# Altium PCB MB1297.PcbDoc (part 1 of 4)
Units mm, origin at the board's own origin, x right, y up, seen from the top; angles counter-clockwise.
Board outline 90.1 x 62.11 mm, 4 copper layers (Top Layer, GND, POWER+GND, Bottom Layer), stack 0.778 mm thick; 235 components, 174 nets, 1727 pads, 1 vias.
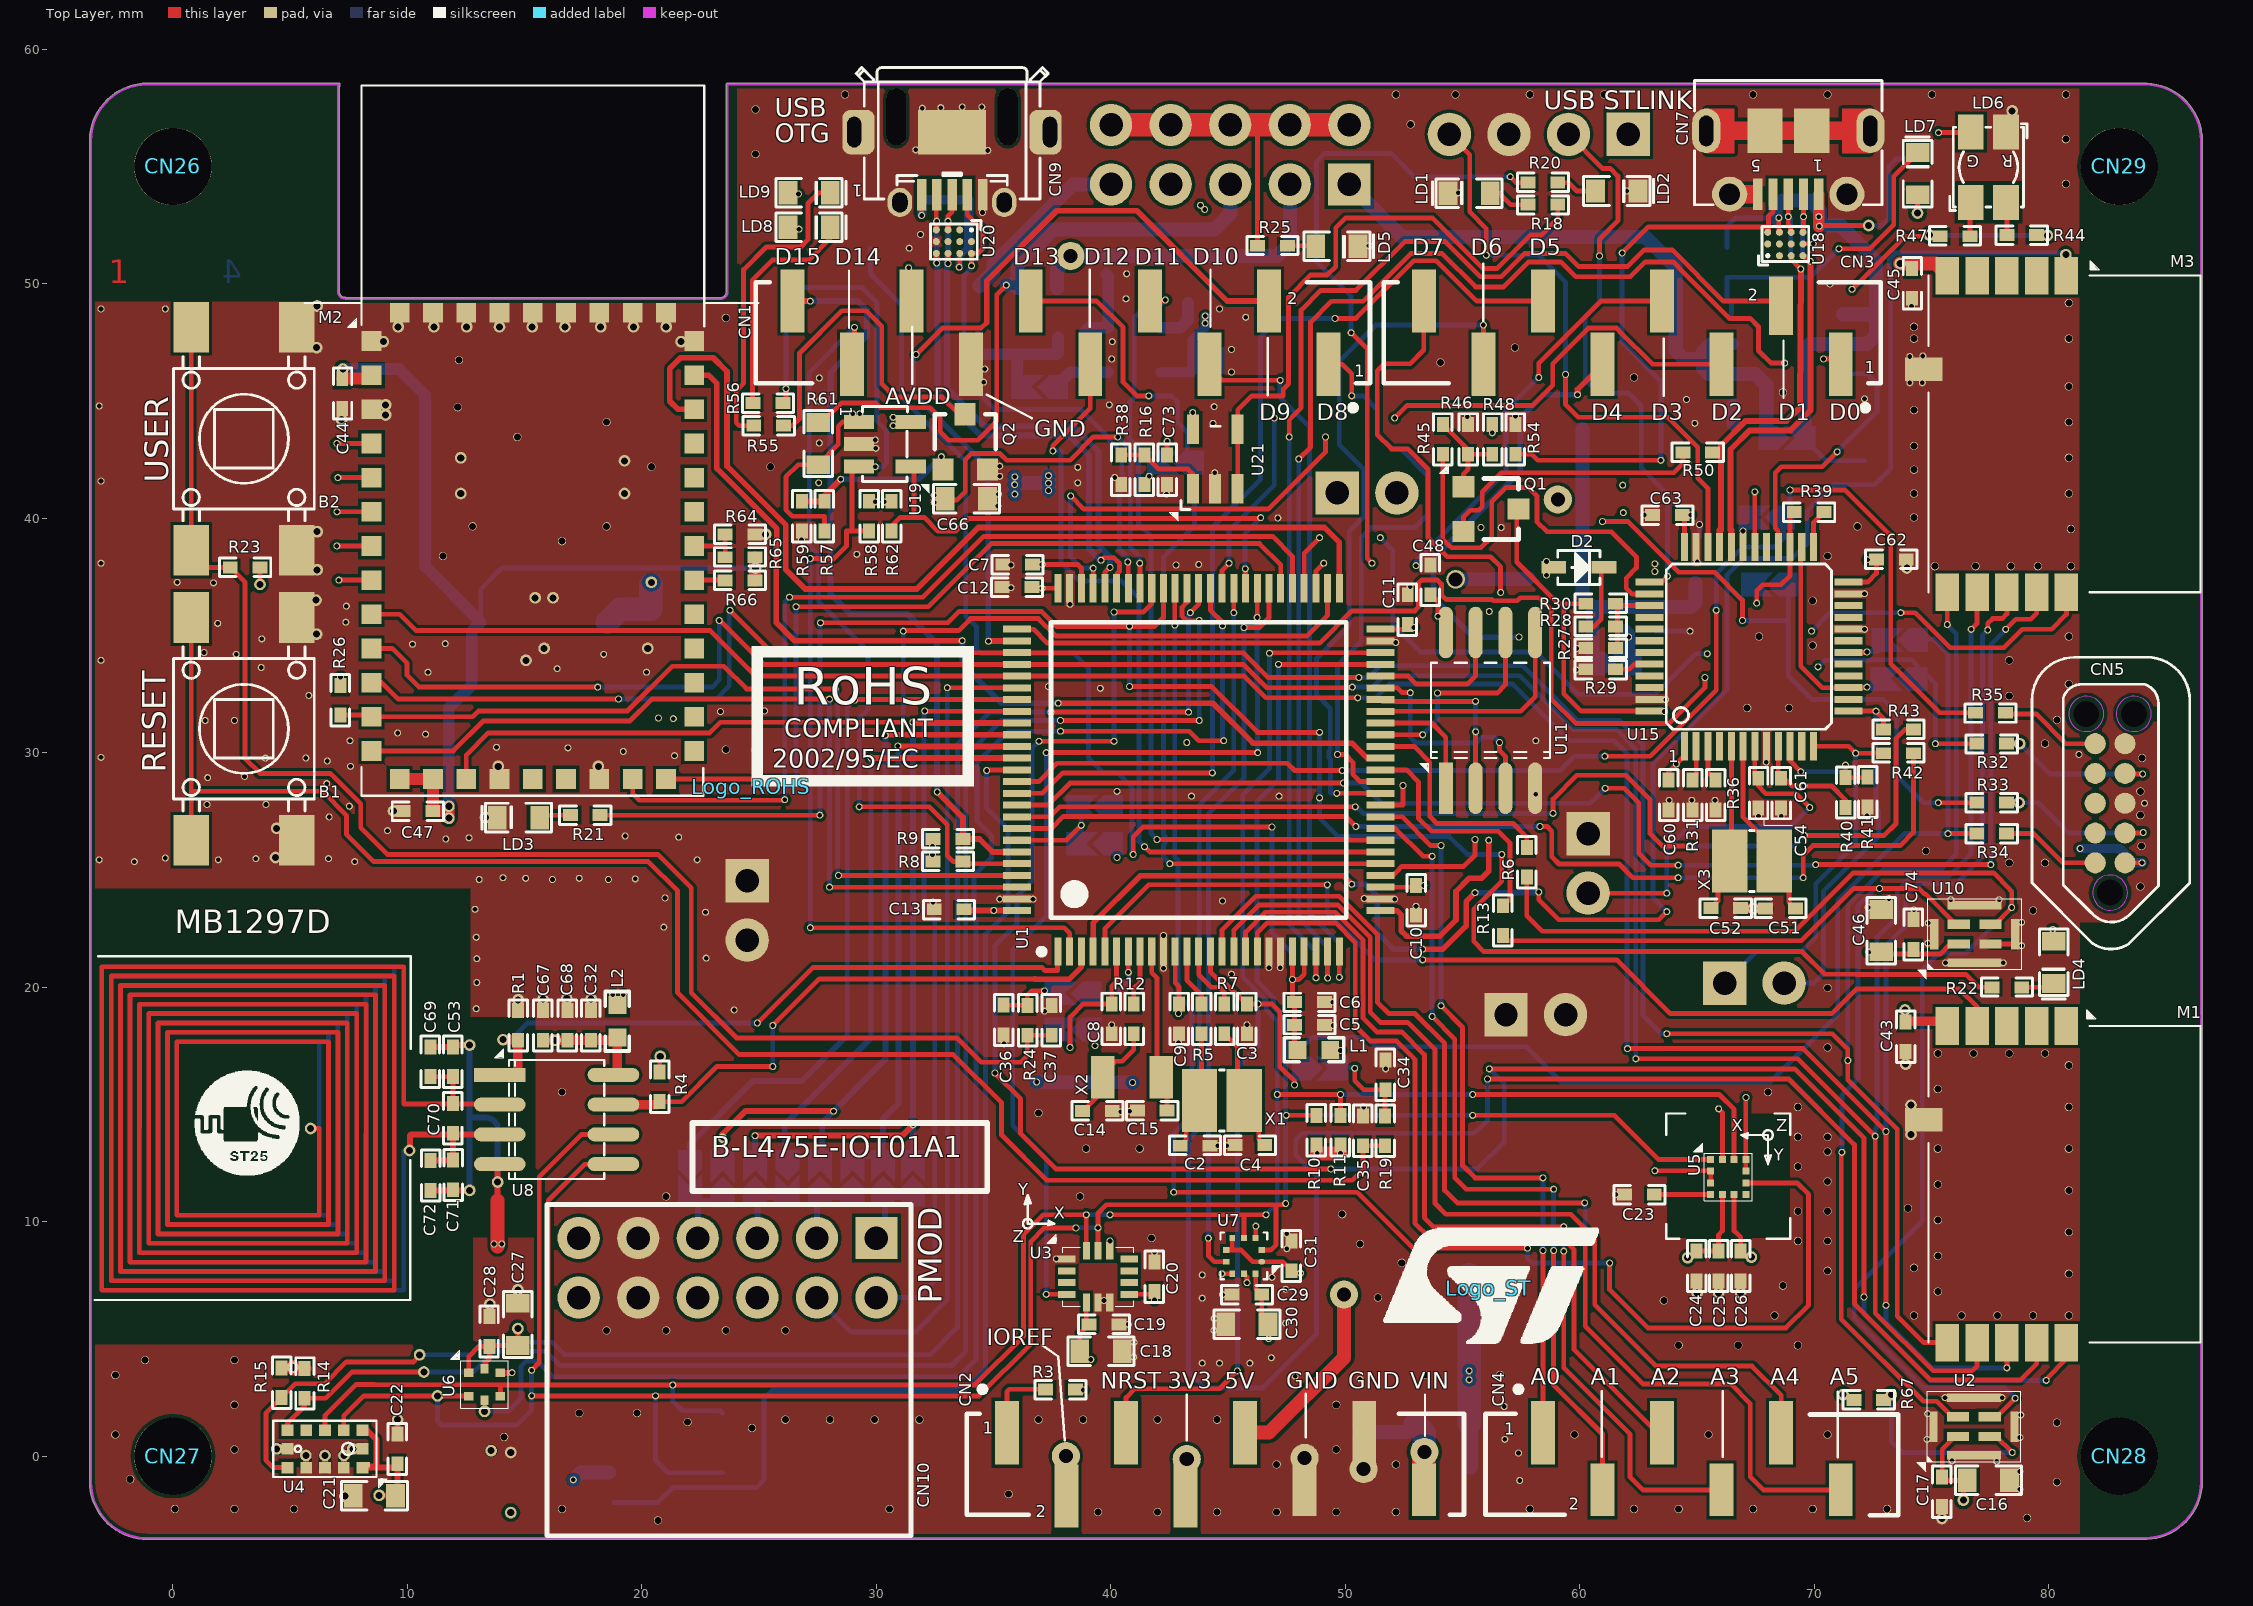
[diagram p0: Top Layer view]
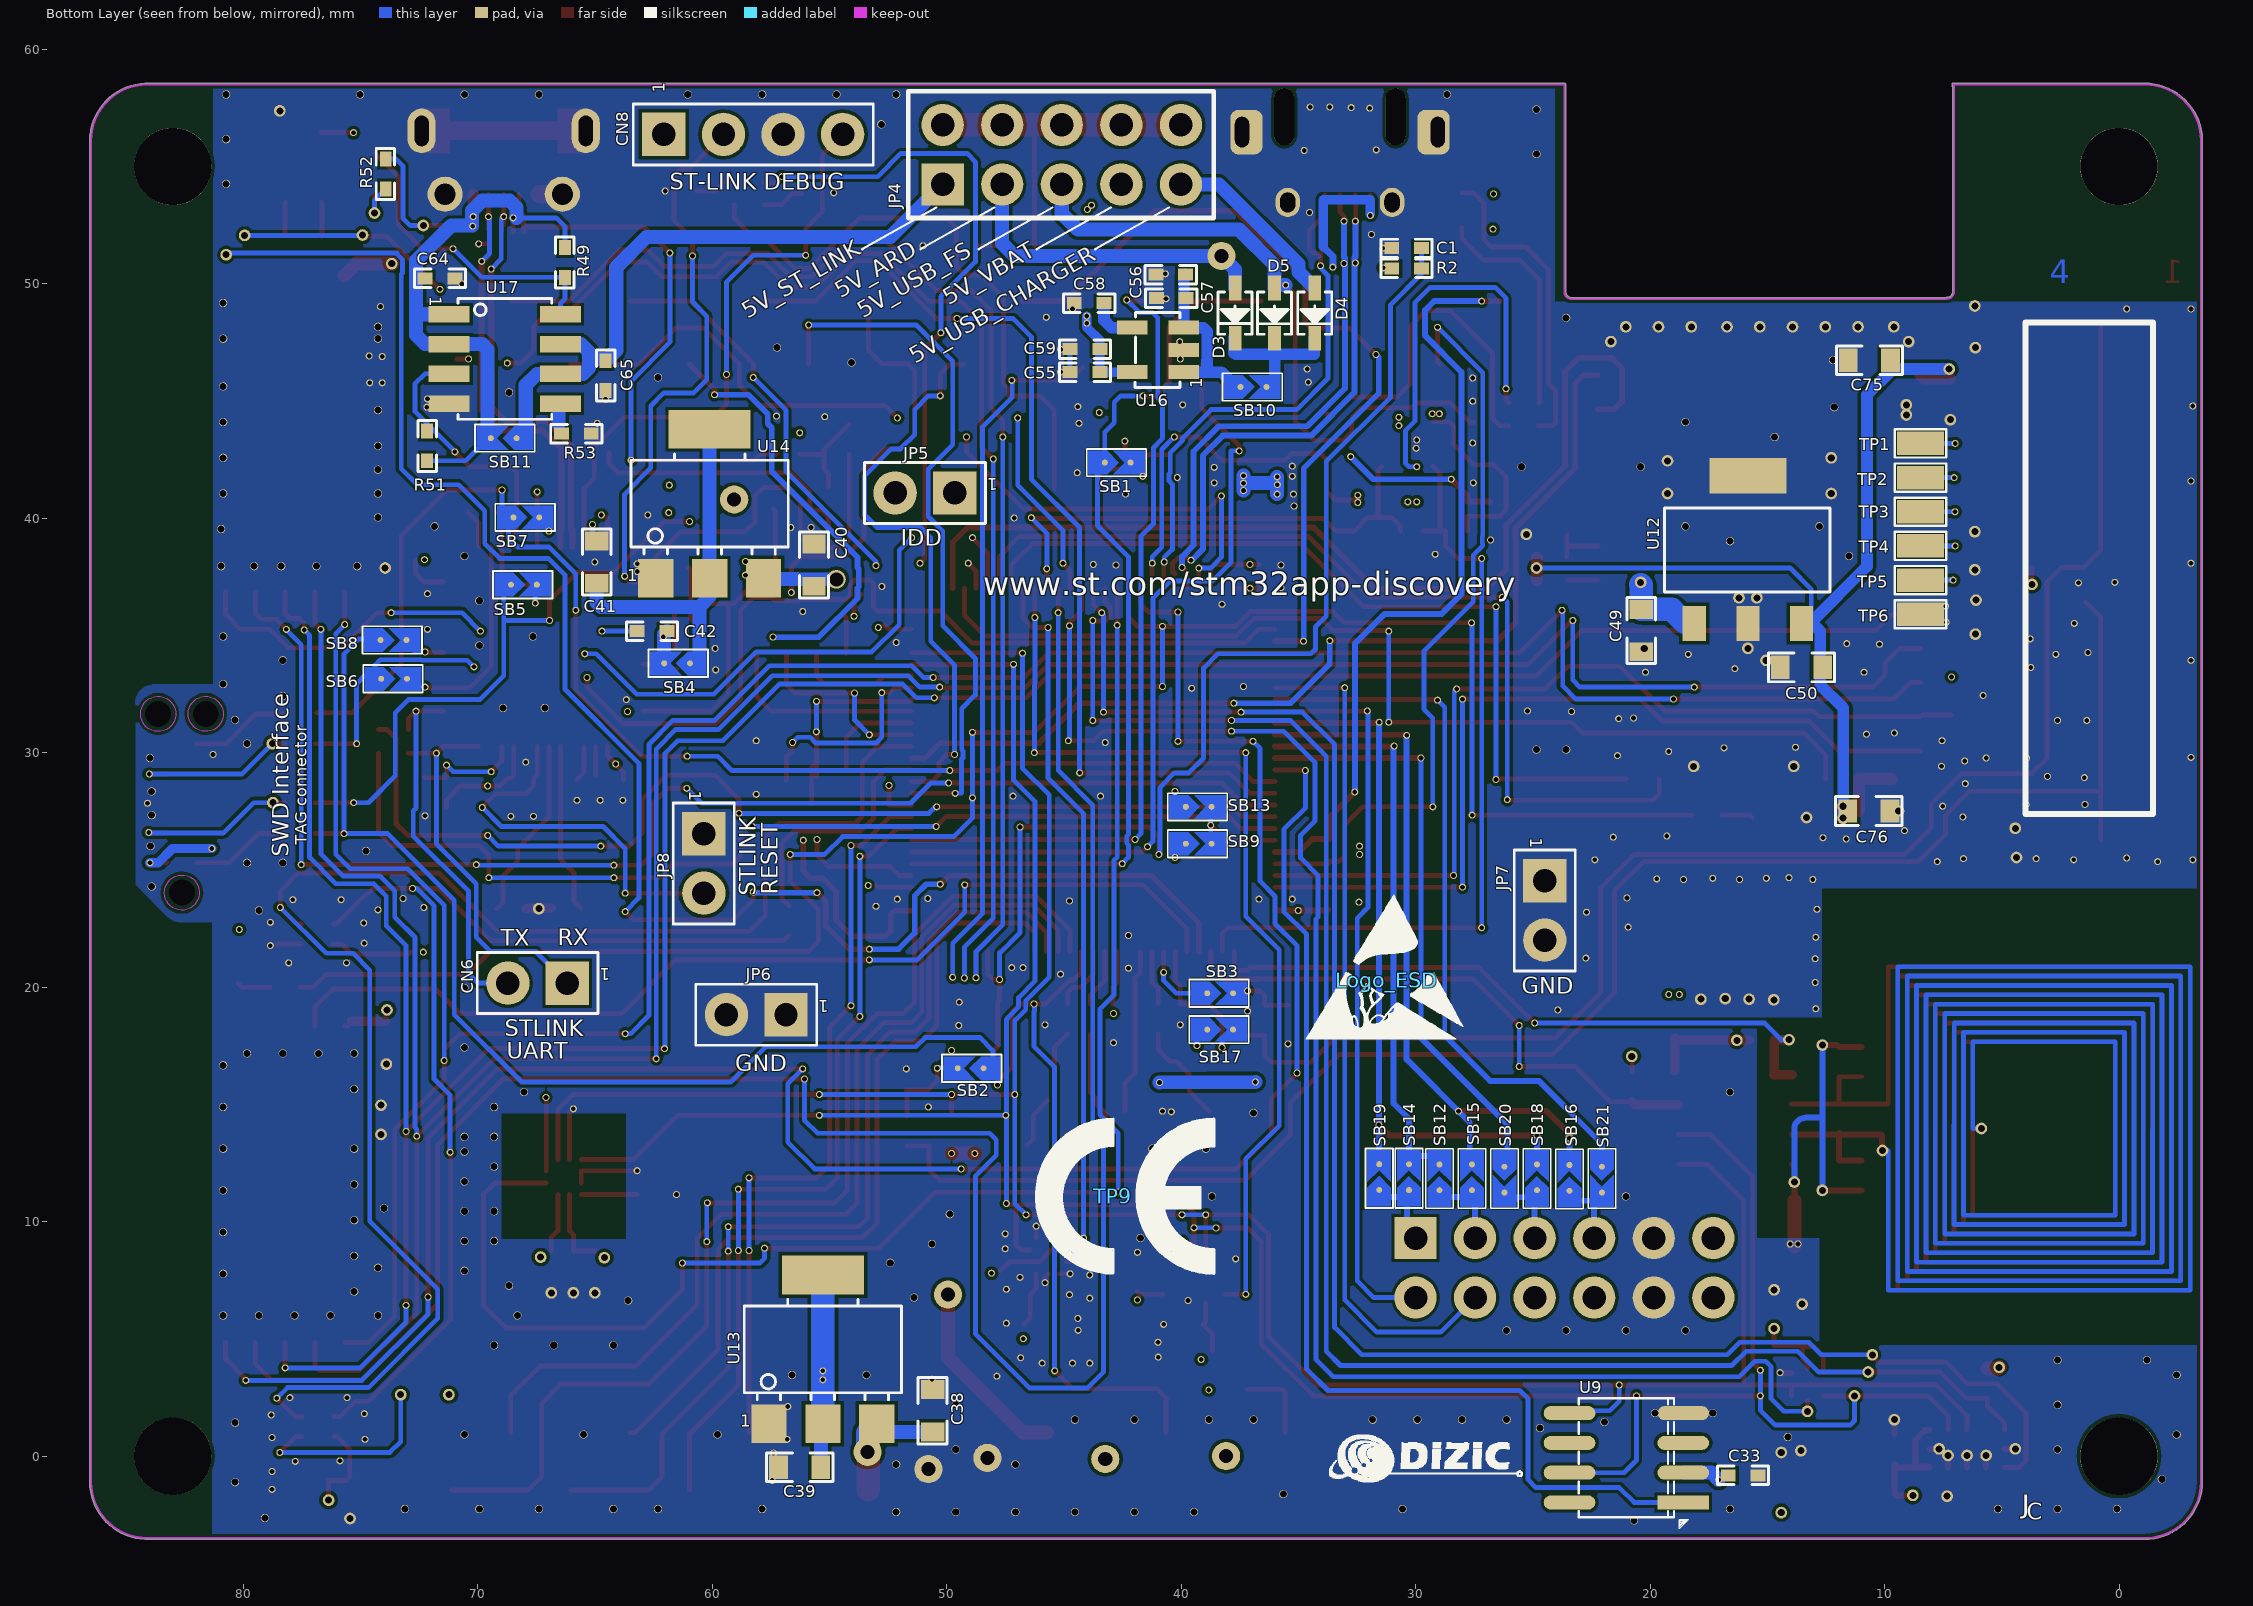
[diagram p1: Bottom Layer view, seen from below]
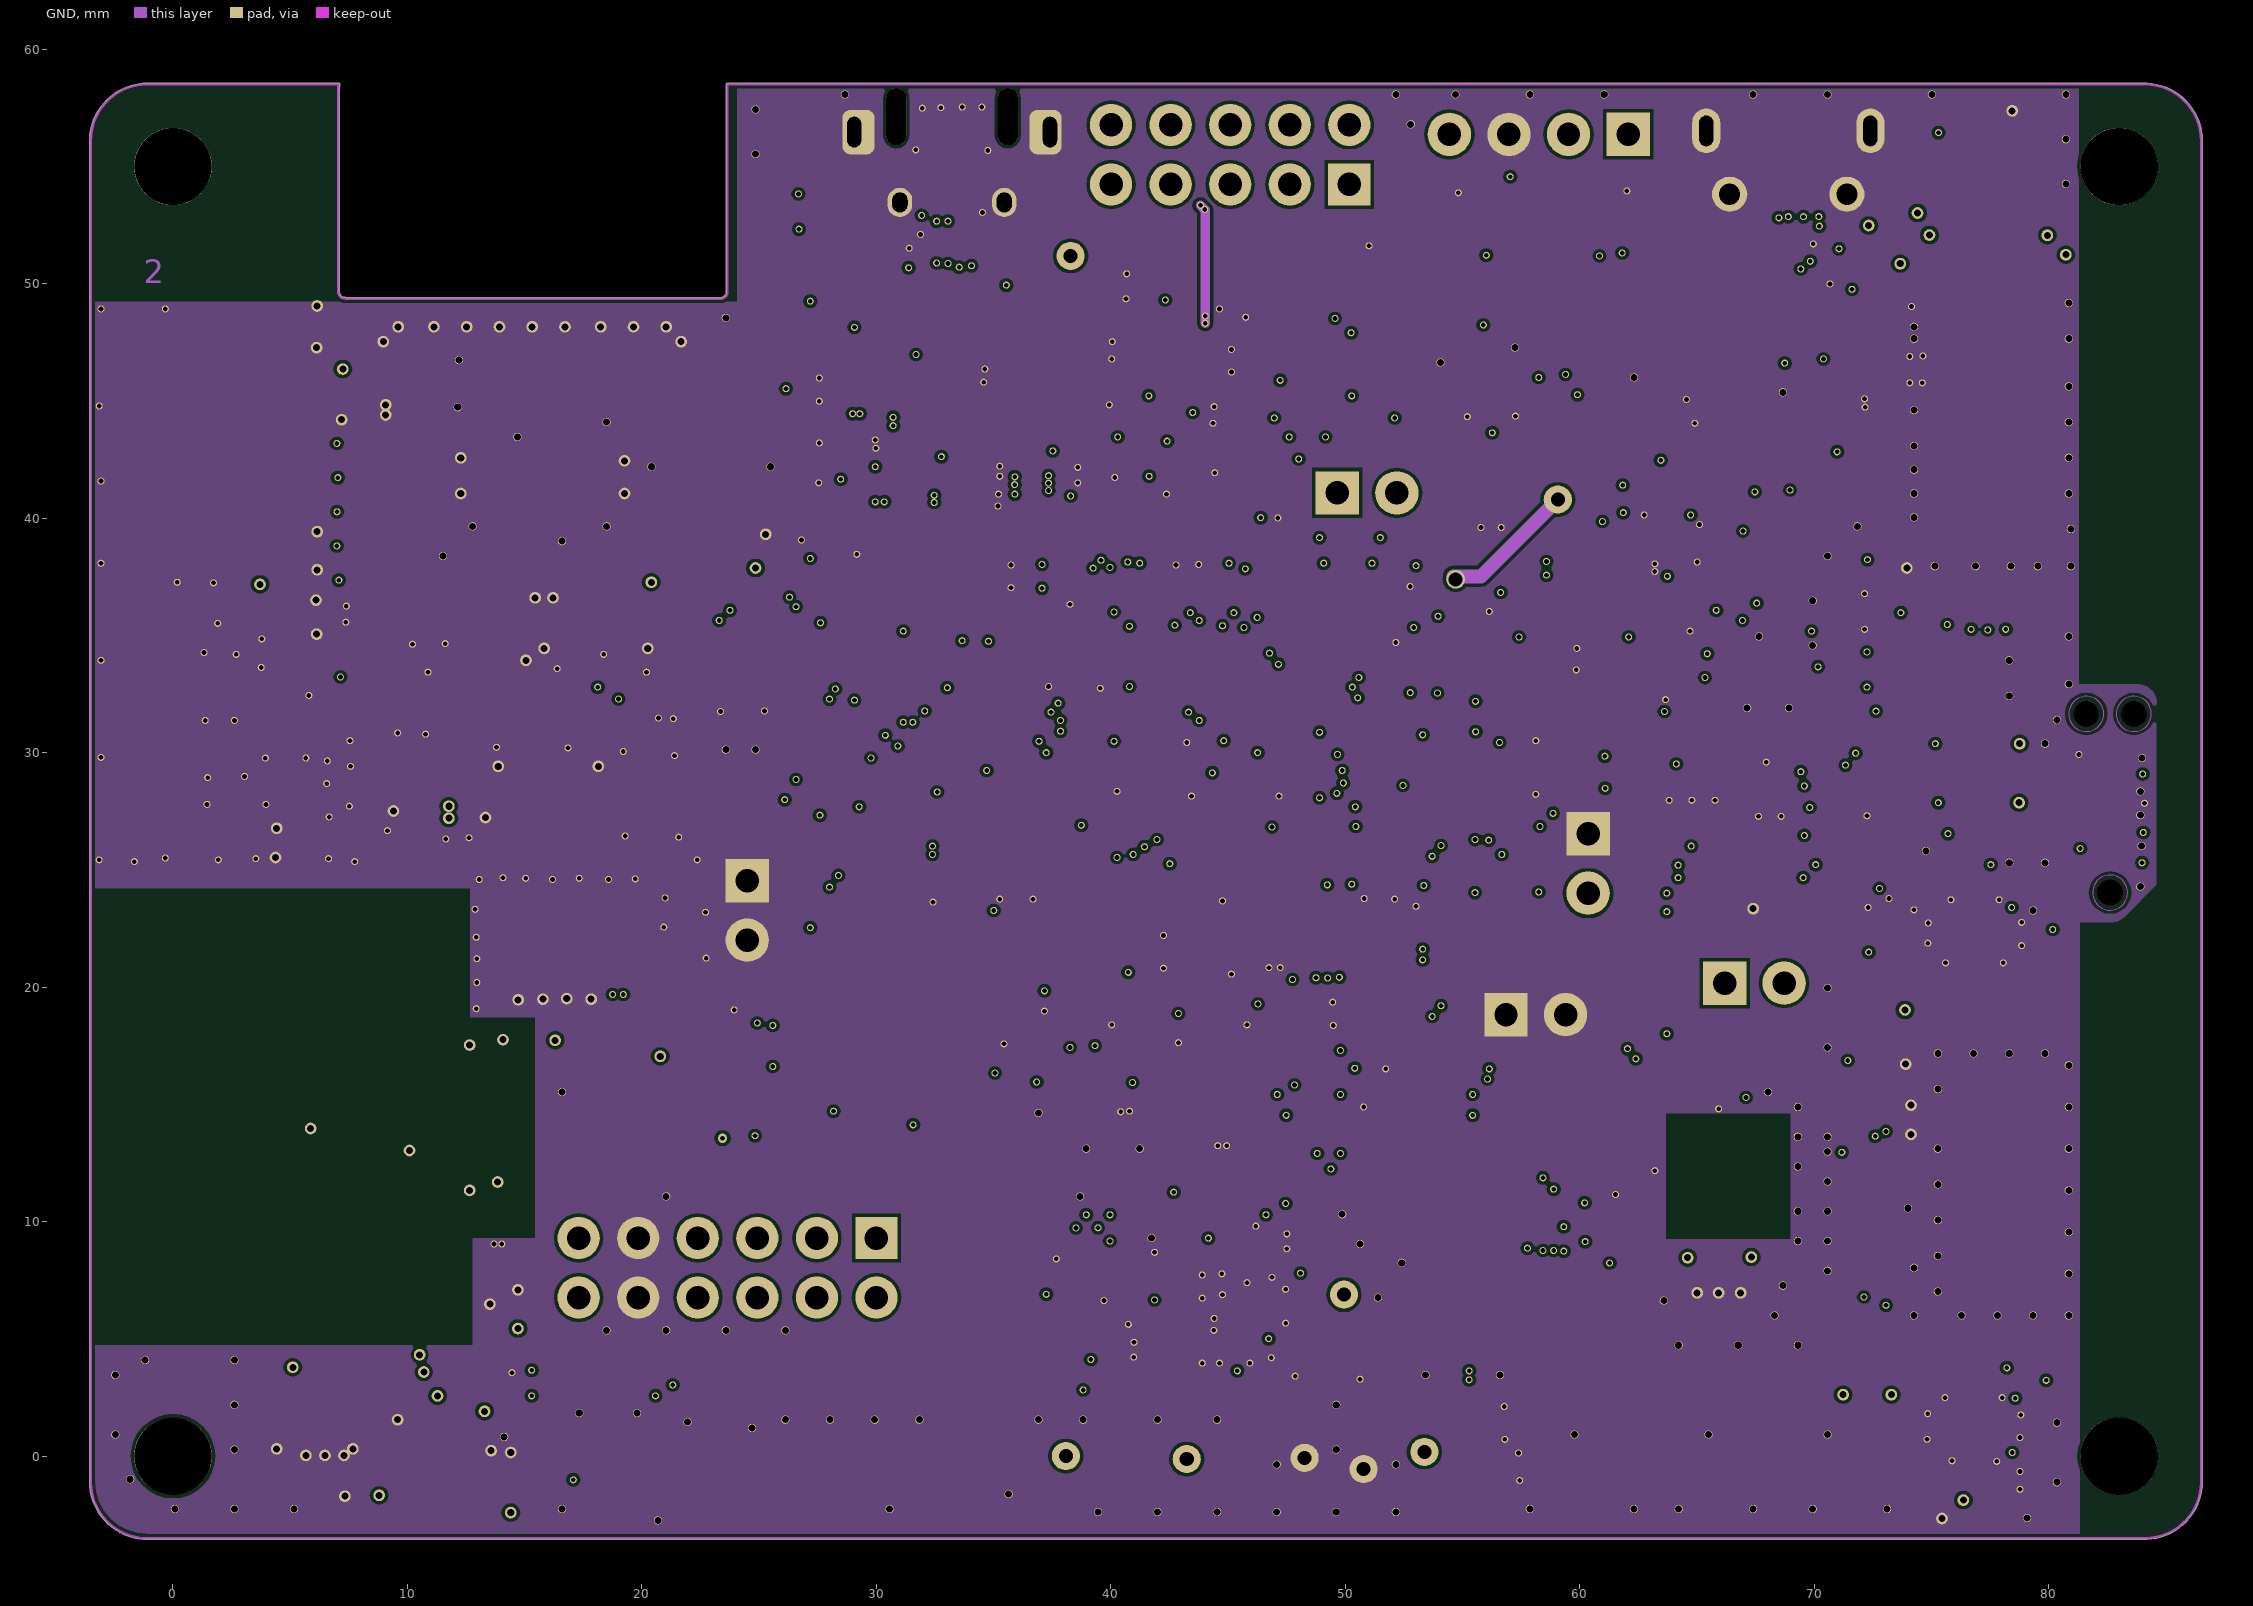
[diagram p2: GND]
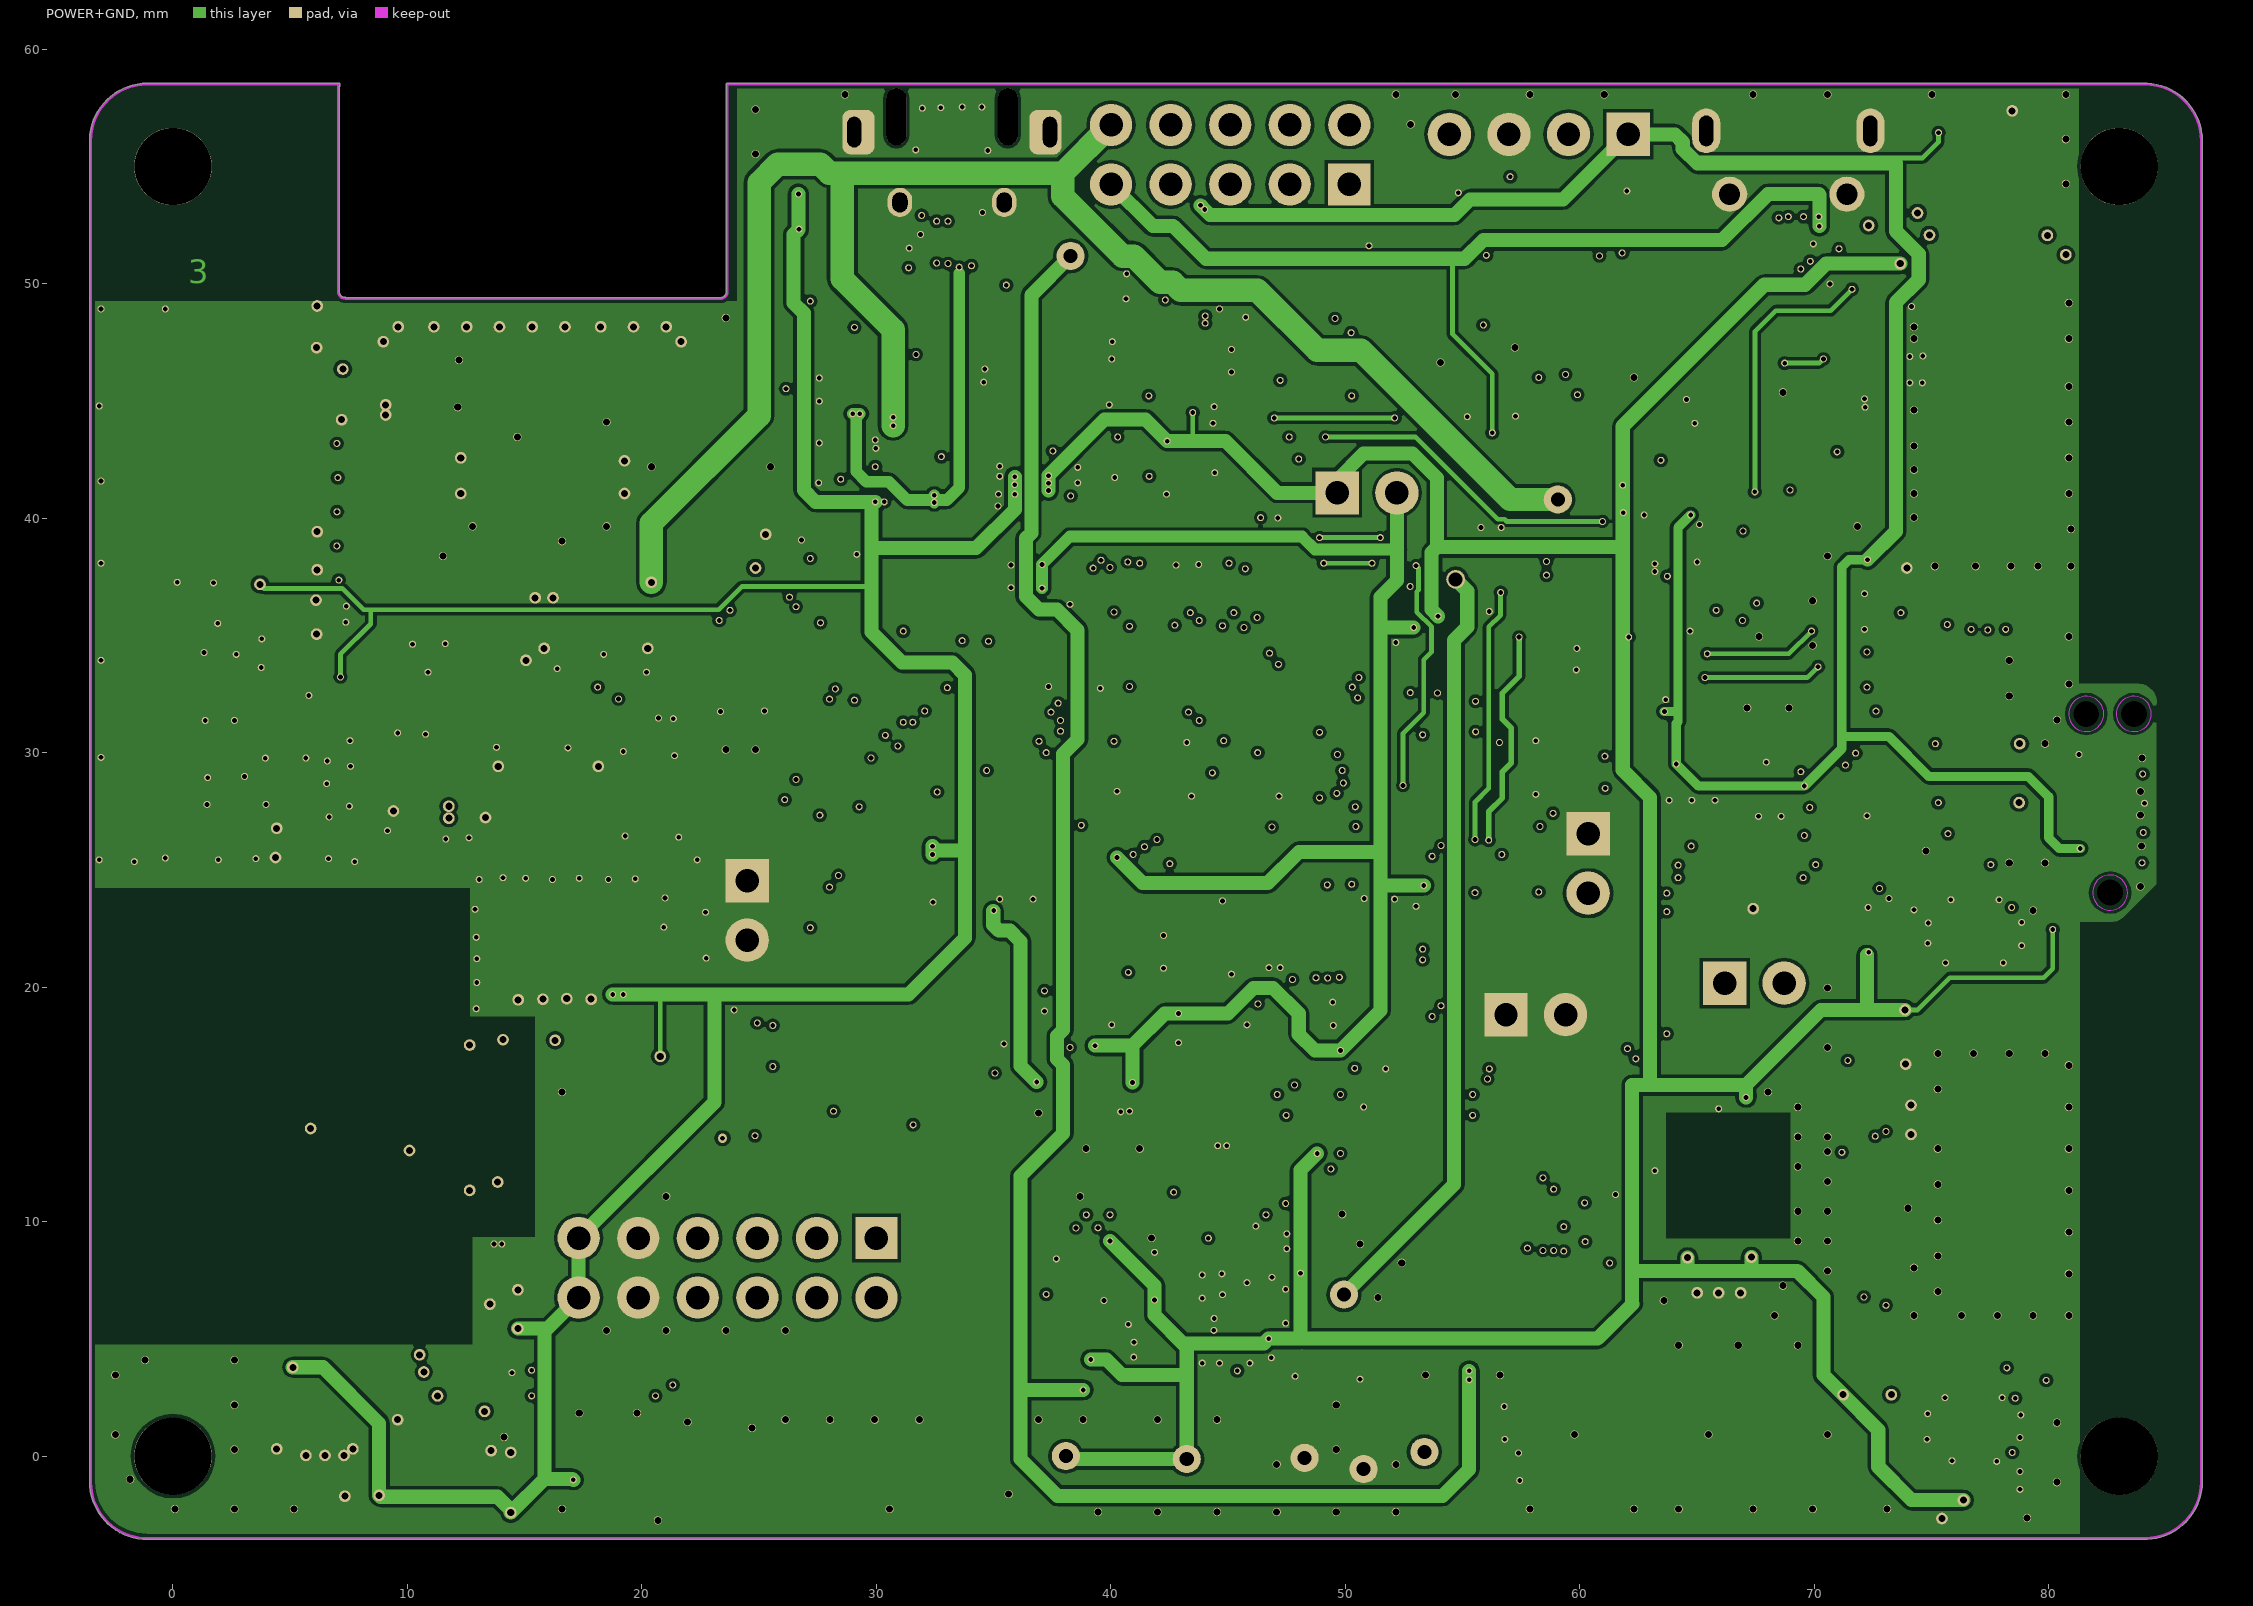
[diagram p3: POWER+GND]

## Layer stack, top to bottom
Top Solder: solder mask 0.0102, Solder Resist, Dk 3.5
Top Layer: signal copper 0.0356
Dielectric1: core 0.254, FR-4, Dk 4.2
GND: signal copper 0.036
Dielectric2: prepreg 0.127, Dk 4.2
POWER+GND: signal copper 0.036
Dielectric3: core 0.254, Dk 4.2
Bottom Layer: signal copper 0.0356
Bottom Solder: solder mask 0.0102, Solder Resist, Dk 3.5

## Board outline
-3.551,-1.089 ccw(c-1.085,-1.089) -1.085,-3.555 ccw(c-1.085,-3.504) -1.066,-3.551 84.073,-3.551 ccw(c84.081,-3.501) 84.081,-3.551 ccw(c84.081,-1.085) 84.131,-3.551 84.182,-3.551 ccw(c84.182,-3.5) 84.197,-3.549 ccw(c84.081,-1.085) 86.546,-1.105 ccw(c86.5,-1.085) 86.55,-1.085 86.55,56.314 ccw(c86.5,56.314) 86.53,56.354 ccw(c84.079,56.085) 84.192,58.549 ccw(c84.181,58.5) 84.181,58.55 84.162,58.55 ccw(c84.079,56.085) 84.079,58.551 ccw(c84.079,58.501) 84.067,58.55 23.652,58.55 ccw(c23.652,58.5) 23.601,58.499 ccw(c23.652,58.499) 23.601,58.499 23.601,49.692 ccw(c23.647,49.671) 23.596,49.668 cw(c23.347,49.658) 23.597,49.658 cw(c23.347,49.658) 23.359,49.408 cw(c23.347,49.658) 23.358,49.408 23.359,49.408 7.383,49.408 ccw(c7.356,49.366) 7.354,49.416 cw(c7.343,49.666) 7.094,49.655 ccw(c7.043,49.652) 7.092,49.664 7.092,58.405 ccw(c7.067,58.449) 7.118,58.449 7.118,58.501 ccw(c7.067,58.501) 7.118,58.501 ccw(c7.067,58.502) 7.118,58.502 ccw(c7.067,58.502) 7.067,58.552 -1.088,58.552 ccw(c-1.088,56.086) -3.541,56.344 ccw(c-3.5,56.315) -3.55,56.315 -3.55,56.224 ccw(c-1.088,56.086) -3.554,56.086 ccw(c-3.504,56.086) -3.55,56.067 -3.55,-1.082 ccw(c-3.5,-1.089)

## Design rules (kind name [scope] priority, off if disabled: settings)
AssemblyTestPointUsage [All] p1 off:
AssemblyTestpoint [All] p1 off: testpointundercomponent=TRUE minsize=1.016 maxsize=2.54 preferedsize=1.524 minholesize=0 maxholesize=1.016 preferedholesize=0.813 testpointgrid=0.025 usegrid=TRUE gridtolerance=0 allowsidetop=TRUE allowsidebottom=TRUE
Clearance Clearance_Poly [InPolygon] p1: gap=0.14
Clearance [All] p2: gap=0.102
ComponentClearance [All] p1 off: gap=0.254 collisioncheckmode=3 verticalgap=0.254 showdistances=FALSE
DiffPairsRouting [All] p1: maxlimit=0.508 minlimit=0.145 mostfreqgap=0.145 toplayer_minwidth=0.381 toplayer_maxwidth=0.381 toplayer_prefwidth=0.381 midlayer1_minwidth=0.381 midlayer1_maxwidth=0.381 midlayer1_prefwidth=0.381 midlayer2_minwidth=0.381 midlayer2_maxwidth=0.381 midlayer2_prefwidth=0.381 bottomlayer_minwidth=0.381 bottomlayer_maxwidth=0.381 bottomlayer_prefwidth=0.381 maxuncoupledlength=12.7
FabricationTestPointUsage [All] p1 off: valid=0 allowmultiple=FALSE
FabricationTestpoint [All] p1 off: side=3 testpointundercomponent=TRUE minsize=1.016 maxsize=2.54 preferedsize=1.524 minholesize=0 maxholesize=1.016 preferedholesize=0.813 testpointgrid=0.025 allowsidetop=TRUE allowsidebottom=TRUE usegrid=TRUE gridtolerance=0
FanoutControl Fanout_BGA [IsBGA] p1 off: bgadir=Out bgaviamode=Centered fanoutstyle=Auto fanoutdirection=Alternating viagrid=0.025 // Fanout_BGA (Default Rule)
FanoutControl Fanout_LCC [IsLCC] p2 off: bgadir=Out bgaviamode=Centered fanoutstyle=Auto fanoutdirection=Alternating viagrid=0.025 // Fanout_LCC (Default Rule)
FanoutControl Fanout_SOIC [IsSOIC] p3 off: bgadir=Out bgaviamode=Centered fanoutstyle=Auto fanoutdirection=Alternating viagrid=0.025 // Fanout_SOIC (Default Rule)
FanoutControl Fanout_Small [(CompPinCount < 5)] p4 off: bgadir=Out bgaviamode=Centered fanoutstyle=Auto fanoutdirection=OutThenIn viagrid=0.025 // Fanout_Small (Default Rule)
FanoutControl Fanout_Default [All] p5 off: bgadir=Out bgaviamode=Centered fanoutstyle=Auto fanoutdirection=Alternating viagrid=0.025 // Fanout_Default (Default Rule)
Height [All] p1 off: minheight=0 maxheight=25.4 prefheight=12.7
HoleSize [All] p1: absolutevalues=TRUE maxlimit=3.3 minlimit=0.2 maxpercent=80.000 minpercent=20.000
HoleToHoleClearance [All] p1 off: gap=0.254 allowstackedmicrovias=TRUE
LayerPairs [All] p1 off: enforce=TRUE
MinimumSolderMaskSliver [All] p1 off: minsoldermaskwidth=0.254
NetAntennae [All] p1 off: netantennaetolerance=0
PasteMaskExpansion [All] p1 off: expansion=0
PolygonConnect [All] p1: connectstyle=Direct reliefconductorwidth=0.254 reliefentries=4 polygonreliefangle="90 Angle" airgapwidth=0.254
RoutingCorners [All] p1 off: cornerstyle=45-Degree minsetback=2.54 maxsetback=2.54
RoutingLayers [All] p1 off: top layer_v5=TRUE mid layer 1_v5=TRUE mid layer 2_v5=TRUE bottom layer_v5=TRUE
RoutingPriority [All] p1 off: routingpriority=0
RoutingTopology [All] p1 off: topology=Shortest
RoutingVias [All] p1: holewidth=0.2 width=0.3 viastyle="Through Hole" minholewidth=0.2 minwidth=0.4 maxholewidth=3.3 maxwidth=3
SilkToSilkClearance [All] p1 off: silktosilkclearance=0.254
SilkToSolderMaskClearance SilkscreenOverComponentPads [IsPad] p1 off: minsilkscreentomaskgap=0.254 clearancetoexposedcopper=TRUE
SolderMaskExpansion [All] p1 off: expansion=0.102
Width [All] p1: maxlimit=6 minlimit=0.102 preferedwidth=0.2
6 further rules are at their usual default settings.

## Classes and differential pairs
component class "USB_OTG_FS  Page 4/11": C66 CN9 IC19 IC20 LD8 LD9 Q2 R55 R56 R57 R58 R59 R61 R62 U19 U20
component class "STLink V2.1 Page 11/11": C51 C52 C54 C55 C56 C57 C58 C59 C60 C61 C62 C63 C64 C65 CN5 CN6 CN7 CN8 D2 D3 D4 D5 IC15 IC16 IC17 IC18 JP8 LD6 LD7 Q1 R27 R28 R29 R30 R31 R32 R33 R34 R35 R36 R37 R39 R40 R41 R42 R43 R44 R45 R46 R47 R48 R49 R50 R51 R52 R53 R54 SB5 SB6 SB7 SB8 SB10 SB11 U15 U16 U17 U18 X3
component class "RF Modules Page 5/11": C43 C44 C45 C47 C48 C49 C50 C75 C76 IC11 M1 M2 M3 R26 R64 R65 R66 TP1 TP2 TP3 TP4 TP5 TP6 U11 U12
component class "Power part Page 8/11": C38 C39 C40 C41 C42 HW1 HW2 HW3 HW4 IC13 IC14 JP4 JP5 JP6 JP7 LD5 R25 SB4 U13 U14
component class "Peripherals Page 10/11": B1 B2 C34 C35 C36 C37 C73 CN10 IC21 LD1 LD2 LD3 LD4 R16 R17 R18 R19 R20 R21 R22 R23 R24 R38 SB1 SB2 SB3 SB12 SB14 SB15 SB16 SB18 SB19 SB20 SB21 U21
component class "NFC & ST-SAFE  Page 7/11": C32 C33 C53 C67 C68 C69 C70 C71 C72 IC8 IC9 L2 R1 R4 U8 U9
component class "MEMS Part Page 6/11": C16 C17 C18 C19 C20 C21 C22 C23 C24 C25 C26 C27 C28 C29 C30 C31 C46 C74 IC2 IC3 IC4 IC5 IC6 IC7 R6 R13 R14 R15 R67 U2 U3 U4 U5 U6 U7 U10
component class "MCU2 Page 3/11": C2 C3 C4 C5 C6 C7 C8 C9 C10 C11 C12 C13 L1 R5 R7 SB9 SB13 SB17 X1
component class "MCU1 Page 2/11": C14 C15 IC1 R8 R9 R10 R11 R12 U1 X2
component class "Arduino Connectors Page 9/11": C1 CN1 CN2 CN3 CN4 R2 R3
differential pair USB: +USB_P -USB_N
differential pair USB_STLK: +USB_STLK_P -USB_STLK_N

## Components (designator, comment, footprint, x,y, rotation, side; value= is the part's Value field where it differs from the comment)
B1 "SW-PUSH-CMS_BLACK" "SWI_WEALTHMETAL_TD-0341_4P - BACK" 3.028,31.018 r0 top
B2 "SW-PUSH-CMS_BLUE" "SWI_WEALTHMETAL_TD-0341_4P - BLUE" 3.028,43.388 r0 top
C1 "100nF" 0402_CAP_NPOL 30.384,51.516 r0 bottom
C2 "Not Fitted (8.2pF)" 0402_CAP_NPOL 43.592,13.238 r0 top
C3 "100nF" 0402_CAP_NPOL 45.801,18.648 r90 top
C4 "Not Fitted (8.2pF)" 0402_CAP_NPOL 45.928,13.264 r180 top
C5 "100nF" 0402_CAP_NPOL 48.468,18.394 r0 top
C6 "1uF" 0402_CAP_NPOL 48.468,19.36 r180 top
C7 "100nF" 0402_CAP_NPOL 36.022,38.029 r180 top
C8 "1uF" 0402_CAP_NPOL 40.036,18.648 r90 top
C9 "100nF" 0402_CAP_NPOL 42.906,18.648 r270 top
C10 "100nF" 0402_CAP_NPOL 53.015,23.703 r270 top
C11 "100nF" 0402_CAP_NPOL 52.659,36.098 r90 top
C12 "100nF" 0402_CAP_NPOL 35.997,37.063 r180 top
C13 "100nF" 0402_CAP_NPOL 33.101,23.322 r180 top
C14 "5.1pF" 0402_CAP_NPOL 39.426,14.711 r0 top
C15 "5.1pF" 0402_CAP_NPOL 41.763,14.737 r180 top
C16 "10uF" 0603_CAP_NPOL 77.424,-1.037 r0 top
C17 "100nF" 0402_CAP_NPOL 75.443,-1.519 r90 top
C18 "4.7uF" 0603_CAP_NPOL 39.578,4.475 r0 top
C19 "100nF" 0402_CAP_NPOL 39.705,5.618 r0 top
C20 "100nF" 0402_CAP_NPOL 41.864,7.65 r90 top
C21 "4.7uF" 0603_CAP_NPOL 8.59,-1.697 r180 top
C22 "100nF" 0402_CAP_NPOL 9.581,0.31 r90 top
C23 "100nF" 0402_CAP_NPOL 62.54,11.155 r180 top
C24 "1uF" 0402_CAP_NPOL 64.978,8.107 r270 top
C25 "100nF" 0402_CAP_NPOL 65.918,8.107 r270 top
C26 "100nF" 0402_CAP_NPOL 66.858,8.107 r270 top
C27 "2.2uF" 0603_CAP_NPOL 14.712,5.618 r90 top
C28 "100nF" 0402_CAP_NPOL 13.493,5.313 r90 top
C29 "100nF" 0402_CAP_NPOL 45.801,6.888 r180 top
C30 "4.7uF" 0603_CAP_NPOL 45.801,5.618 r180 top
C31 "100nF" 0402_CAP_NPOL 47.706,8.539 r90 top
C32 "100nF" 0402_CAP_NPOL 17.836,18.369 r90 top
C33 "100nF" 0402_CAP_NPOL 16.033,-0.833 r180 bottom
C34 "100nF" 0402_CAP_NPOL 51.72,16.261 r90 top
C35 "10pF" 0402_CAP_NPOL 50.754,13.873 r90 top
C36 "100nF" 0402_CAP_NPOL 35.413,18.598 r270 top
C37 "10pF" 0402_CAP_NPOL 37.479,18.587 r90 top
C38 "10uF" 0603_CAP_NPOL 50.602,1.935 r90 bottom
C39 "10uF" 0603_CAP_NPOL 56.266,-0.478 r0 bottom
C40 "10uF" 0603_CAP_NPOL 55.657,38.003 r90 bottom
C41 "10uF" 0603_CAP_NPOL 64.928,38.13 r90 bottom
C42 "100nF" 0402_CAP_NPOL 62.565,35.184 r0 bottom
C43 "100nF" 0402_CAP_NPOL 73.894,17.886 r270 top
C44 "100nF" 0402_CAP_NPOL 7.219,45.318 r270 top
C45 "100nF" 0402_CAP_NPOL 74.174,50.017 r270 top
C46 "10uF" 0603_CAP_NPOL 72.852,22.408 r90 top
C47 "100nF" 0402_CAP_NPOL 10.445,27.513 r180 top
C48 "100nF" 0402_CAP_NPOL 53.625,37.368 r90 top
C49 "10uF" 0603_CAP_NPOL 20.376,35.209 r270 bottom
C50 "10uF" 0603_CAP_NPOL 13.543,33.634 r0 bottom
C51 "10pF" 0402_CAP_NPOL 68.56,23.347 r0 top
C52 "10pF" 0402_CAP_NPOL 66.223,23.373 r180 top
C53 "10pF" 0402_CAP_NPOL 11.943,16.82 r90 top
C54 "100nF" 0402_CAP_NPOL 67.607,28.275 r270 top
C55 "100nF" 0402_CAP_NPOL 44.1,46.233 r0 bottom
C56 "1uF" 0402_CAP_NPOL 40.442,50.398 r0 bottom
C57 "100nF" 0402_CAP_NPOL 40.42,49.385 r0 bottom
C58 "10nF" 0402_CAP_NPOL 43.922,49.179 r0 bottom
C59 "1uF" 0402_CAP_NPOL 44.1,47.223 r0 bottom
C60 "100nF" 0402_CAP_NPOL 63.785,28.199 r270 top
C61 "100nF" 0402_CAP_NPOL 68.573,28.275 r270 top
C62 "100nF" 0402_CAP_NPOL 73.284,38.232 r0 top
C63 "100nF" 0402_CAP_NPOL 63.734,40.137 r180 top
C64 "1uF" 0402_CAP_NPOL 71.608,50.221 r180 bottom
C65 "100nF" 0402_CAP_NPOL 64.547,46.08 r270 bottom
C66 "4.7uF" 0603_CAP_NPOL 33.838,40.823 r0 top
C67 "100pF" 0402_CAP_NPOL 15.779,18.369 r90 top
C68 "1uF" 0402_CAP_NPOL 16.82,18.369 r90 top
C69 "Not Fitted" 0402_CAP_NPOL 10.978,16.82 r90 top
C70 "Not Fitted" 0402_CAP_NPOL 11.943,14.407 r90 top
C71 "10pF" 0402_CAP_NPOL 11.943,11.994 r270 top
C72 "Not Fitted" 0402_CAP_NPOL 10.978,11.968 r270 top
C73 "100nF" 0402_CAP_NPOL 42.398,42.067 r270 top
C74 "100nF" 0402_CAP_NPOL 74.224,22.25 r90 top
C75 "2.2uF" 0603_CAP_NPOL 10.648,46.741 r0 bottom
C76 "2.2uF" 0603_CAP_NPOL 10.673,27.513 r180 bottom
CN1 "Header 10X1_Female_SMD" F-V50XC-1X10R-LF 37.852,47.911 r0 top locked
CN2 "Header 8X1_Female_SMD" F-V50XC-1X08R-LF#1 44.456,-0.349 r180 top locked
CN3 "Header 8X1_Female_SMD" F-V50XC-1X08R-LF#2 62.236,47.911 r0 top locked
CN4 "Header 6X1_Female_SMD" F-V50XC-1X06R-LF 64.776,-0.349 r180 top locked
CN5 "TC2050-IDC-NL" CON_TAG-C_TC2050-IDC-NL 82.614,27.843 r90 top
CN6 "header 2 pins 2.54mm" CON_SAMTEC_TSW-102-07-G-S 67.442,20.172 r0 bottom
CN7 "1050170001" CON_USBMICROB_MOLEX_105017-0001_H2P90 68.89,57.968 r180 top
CN8 "Header 4 pins" CON_SAMTEC_TSW-104-07-G-S 58.247,56.367 r180 bottom
CN9 "475900001" CON_USBMICROAB_MOLEX_47590-0001_H3 33.228,57.917 r180 top
CN10 "HEADER_2X6_PMOD" "Header F 2x6x2.54 TH H PMOD" 30.003,9.301 r180 top
CN26 "Comment" "Spacer+Nut M3" 0,55 r90 top
CN27 "Comment" "Spacer+Nut M3" 0,0 r90 top
CN28 "Comment" "Spacer+Nut M3" 83,0 r90 top
CN29 "Comment" "Spacer+Nut M3" 83,55 r90 top
D2 "BAT60JFILM" DIO_SOD323 59.956,37.902 r0 top
D3 "BAT60JFILM" DIO_SOD323 37.699,48.747 r270 bottom
D4 "BAT60JFILM" DIO_SOD323 34.302,48.746 r270 bottom
D5 "BAT60JFILM" DIO_SOD323 36.017,48.746 r270 bottom
JP4 "HEADER_2X5" "Header M 2x5x2.54 TH V" 50.17,54.234 r180 bottom
JP5 "Jumper_2.54mm" CON_SAMTEC_TSW-102-07-G-S 50.928,41.077 r0 bottom
JP6 "Jumper_2.54mm" CON_SAMTEC_TSW-102-07-G-S 58.12,18.826 r0 bottom
JP7 "Jumper_2.54mm" CON_SAMTEC_TSW-102-07-G-S 24.491,23.275 r270 bottom
JP8 "Jumper_2.54mm" CON_SAMTEC_TSW-102-07-G-S 60.356,25.278 r270 bottom
L1 "FCM1608KF-601T03" 0603L 48.659,17.328 r0 top
L2 "742792042" 0603L 18.954,18.547 r270 top
LD1 "LED" 0603_LED_GREEN 55.276,53.853 r0 top
LD2 "LED" 0603_LED_GREEN 61.575,53.954 r180 top
LD3 "LED" 0603_LED_Yellow 14.737,27.234 r0 top
LD4 "LED" 0603_LED_Blue 80.218,21.061 r90 top
LD5 "LED" 0603_LED_GREEN 49.637,51.592 r180 top
LD6 "LD_BICOLOR_CMS" LED_BI-GR_HSMF-A201-A00J1 77.424,54.97 r180 top
LD7 "LED" 0603_LED_RED 74.402,54.691 r270 top
LD8 "LED" 0603_LED_RED 27.132,52.405 r180 top
LD9 "LED" 0603_LED_GREEN 27.132,53.878 r180 top
Logo_ESD "Comment" SYMBOL_ESD 31.222,20.299 r180 bottom
Logo_ROHS "Comment" SYMBOL_RoHS 24.669,28.554 r0 top
Logo_ST "Comment" LOGO_ST_Size3 56.114,7.168 r0 top
M1 "BT Module" SPBTLE-RF 80.752,18.344 r270 top
M2 "ISM43362-M3G-L44" ISM43362-M3G-L44 15.347,38.816 r90 top locked
M3 "SPSGRF" SPSGRF 80.752,50.348 r270 top
Q1 "BSR14" SOT23-3 57.384,40.391 r270 top
Q2 "BSR14" SOT23-3 33.787,44.429 r0 top
R1 "30K" 0402_RES 14.712,18.369 r270 top
R2 "0R" 0402_RES 30.384,50.652 r180 bottom
R3 "1K" 0402_RES 37.851,2.85 r180 top
R4 "20K" 0402_RES 20.757,15.753 r270 top
R5 "Not Fitted (0R)" 0402_RES 43.871,18.648 r270 top
R6 "0R" 0402_RES 57.739,25.329 r90 top
R7 "Not Fitted (0R)" 0402_RES 44.836,18.648 r270 top
R8 "2K2" 0402_RES 33.051,25.354 r0 top
R9 "2K2" 0402_RES 33.051,26.319 r0 top
R10 "2K2" 0402_RES 48.773,13.899 r90 top
R11 "2K2" 0402_RES 49.789,13.899 r90 top
R12 "0R" 0402_RES 40.975,18.648 r270 top
R13 "0R" 0402_RES 56.723,22.839 r90 top
R14 "10K" 0402_RES 5.619,3.104 r270 top
R15 "10K" 0402_RES 4.628,3.129 r270 top
R16 "10K" 0402_RES 41.433,42.067 r90 top
R18 "1K" 0402_RES 58.425,53.37 r180 top
R19 "1K" 0402_RES 51.694,13.873 r270 top
R20 "330R" 0402_RES 58.425,54.31 r0 top
R21 "1K" 0402_RES 17.582,27.335 r180 top
R22 "680R" 0402_RES 78.212,19.995 r0 top
R23 "100K" 0402_RES 3.079,37.902 r0 top
R24 "1K" 0402_RES 36.438,18.587 r270 top
R25 "330R" 0402_RES 46.894,51.618 r0 top
R26 "47K" 0402_RES 7.143,32.237 r90 top
R27 "4K7" 0402_RES 60.889,34.473 r180 top
R28 "2K7" 0402_RES 60.889,35.387 r0 top
R29 "100K" 0402_RES 60.889,33.558 r180 top
R30 "Not Fitted (0R)" 0402_RES 60.889,36.352 r0 top
R31 "10K" 0402_RES 64.801,28.199 r270 top
R32 "22R" 0402_RES 77.564,30.383 r180 top
R33 "22R" 0402_RES 77.564,27.869 r180 top
R34 "22R" 0402_RES 77.564,26.548 r180 top
R35 "22R" 0402_RES 77.513,31.704 r180 top
R36 "Not Fitted (10K)" 0402_RES 65.791,28.199 r270 top
R38 "200K" 0402_RES 40.442,42.067 r90 top
R39 "100R" 0402_RES 69.779,40.264 r180 top
R40 "4K7" 0402_RES 71.328,28.3 r270 top
R41 "4K7" 0402_RES 72.268,28.326 r270 top
R42 "0R" 0402_RES 73.589,29.977 r0 top
R43 "0R" 0402_RES 73.589,30.993 r0 top
R44 "330R" 0402_RES 78.847,52.075 r180 top
R45 "100R" 0402_RES 54.158,43.363 r90 top
R46 "36K" 0402_RES 55.225,43.363 r270 top
R47 "330R" 0402_RES 76.002,52.024 r0 top
R48 "10K" 0402_RES 56.266,43.363 r270 top
R49 "100K" 0402_RES 66.274,50.906 r90 bottom
R50 "1K5" 0402_RES 65.029,42.804 r0 top
R51 "10K" 0402_RES 72.167,43.083 r270 bottom
R52 "1K" 0402_RES 73.919,54.678 r90 bottom
R53 "2K2" 0402_RES 65.791,43.617 r0 bottom
R54 "100K" 0402_RES 57.257,43.363 r90 top
R55 "330R" 0402_RES 25.405,43.947 r180 top
R56 "1K" 0402_RES 25.38,44.912 r180 top
R57 "47K" 0402_RES 27.788,40.086 r90 top
R58 "47K" 0402_RES 29.683,40.086 r270 top
R59 "100K" 0402_RES 26.828,40.086 r90 top
R61 "0R" 0603_RES 27.513,43.185 r270 top
R62 "47K" 0402_RES 30.643,40.086 r270 top
R64 "Not Fitted (10K)" 0402_RES 24.186,39.299 r0 top
R65 "Not Fitted (10K)" 0402_RES 24.186,38.333 r0 top
R66 "Not Fitted (10K)" 0402_RES 24.186,37.343 r0 top
R67 "10K" 0402_RES 72.319,2.392 r0 top
SB1 "Close" SB 42.753,42.372 r180 bottom
SB2 "Close" SB 48.926,16.54 r0 bottom
SB3 "Close" SB 38.385,19.741 r180 bottom
SB4 "Close" SB 61.448,33.812 r0 bottom
SB5 "Close" SB 68.077,37.165 r180 bottom
SB6 "Close" SB 73.614,33.152 r180 bottom
SB7 "Close" SB 67.976,40.035 r180 bottom
SB8 "Close" SB 73.64,34.803 r180 bottom
SB9 "Open" SB 39.299,26.116 r180 bottom
SB10 "Close" SB 36.962,45.598 r180 bottom
SB11 "Open" SB 68.839,43.413 r0 bottom
SB12 "Open" SB 28.983,11.841 r90 bottom
SB13 "Close" SB 39.299,27.691 r180 bottom
SB14 "Close" SB 30.282,11.847 r90 bottom
SB15 "Close" SB 27.597,11.841 r90 bottom
SB16 "Open" SB 23.439,11.816 r90 bottom
SB17 "Close" SB 38.385,18.191 r180 bottom
SB18 "Close" SB 24.825,11.841 r90 bottom
SB19 "Open" SB 31.552,11.851 r90 bottom
SB20 "Open" SB 26.211,11.841 r270 bottom
SB21 "Close" SB 22.052,11.841 r270 bottom
TP1 "PT" PTB 8.472,43.187 r180 bottom
TP2 "PT" PTB 8.472,41.73 r180 bottom
TP3 "PT" PTB 8.472,40.273 r180 bottom
TP4 "PT" PTB 8.472,38.816 r180 bottom
TP5 "PT" PTB 8.472,37.359 r180 bottom
TP6 "PT" PTB 8.472,35.902 r180 bottom
TP9 "Comment" "LOGO CE" 42.913,11.088 r180 bottom
U1 "STM32L475VGTx" "LQFP100 14x14x1.6" 43.744,29.266 r90 top
U2 "MP34DT01-M" "HCLGA-4LD 3x4x1" 76.807,1.262 r90 top
U3 "LSM6DSL" LGA14L-2.5X3X0.86p0.5 39.451,7.65 r0 top
U4 "VL53L0X" LGA12-optical 6.482,0.31 r0 top
U5 "LIS3MDL" VFLGA12-2x2x1 66.329,11.904 r0 top
U6 "HTS221" HLGA6L-2x2x0.9 13.289,3.053 r0 top
U7 "LPS22HB" HLGA10L-2X2X0.76 45.674,8.539 r180 top
U8 "M24SR64-Y" SOP8 16.363,14.356 r0 top
U9 "STSAFE-A100 (Not Fitted)" SOP8 21.011,-0.071 r0 bottom
U10 "MP34DT01-M" "HCLGA-4LD 3x4x1" 76.84,22.266 r90 top
U11 "MX25R6435F" SOP8L 56.19,31.806 r90 top
U12 "LT1963EST-3.3" SOT223_SC73 15.829,38.664 r180 bottom
U13 "LD1117S50TR" REG_SOT223-TAB 55.28,4.551 r180 bottom
U14 "LD1117S33TR" REG_SOT223-TAB 60.106,40.619 r180 bottom
U15 "STM32F103CBT6" ICC_LQFP48_7X7_P050 67.214,34.523 r0 top
U16 "LD3985M33R" REG_SOT23-5L 40.993,47.176 r90 bottom
U17 "ST890CDR" ICC_SO8_5X4_P127 68.839,46.792 r270 bottom
U18 "EMIF02-USB03F2" ESD_FLIP-CHIP-BGA11_1P44X1P94_P050 68.763,51.694 r90 top
U19 "STMPS2141STR" MOS_SOT23-5L 30.358,43.159 r270 top
U20 "EMIF02-USB03F2" ESD_FLIP-CHIP-BGA11_1P44X1P94_P050 33.305,51.795 r270 top
U21 "TSV631AILT" SOT23-5 44.455,42.524 r90 top
X1 "Not Fitted (NX3225GD-8.00M)" CRY_NX3225GD_2P 44.735,15.169 r180 top
X2 "NX3215SA-32.768K" CRY_NX3215SA_2P 40.899,16.159 r0 top
X3 "NX3225GD-8.00M" CRY_NX3225GD_2P 67.341,25.379 r180 top

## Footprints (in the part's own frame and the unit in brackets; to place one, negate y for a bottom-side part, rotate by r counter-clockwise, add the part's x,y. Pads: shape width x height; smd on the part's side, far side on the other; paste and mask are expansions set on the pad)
0402_CAP_NPOL [mil] "Capacitor FootPrint 0402"
  rect 25x20 smd: 1(-25,0) 2(25,0)
  silkscreen extent -43,-15 43,16, body extent -39,-14 41,14, height 32
0402_RES [mil] "Resistor FootPrint 0402"
  rect 25x20 smd: 1(-25,0) 2(25,0)
  silkscreen extent -43,-15 43,16, body extent -38,-11 39,13, height 16
0603_CAP_NPOL [mm] "Capacitor FootPrint 0603"
  rect 0.8x1 smd: 1(-0.902,0) 2(0.902,0)
  silkscreen extent -1.41,-0.61 1.41,0.61, body extent -1.28,-0.46 1.26,0.48, height 0.82
0603_LED_Blue [mm] "Resistor Footprint 0603"
  rect 0.8x1 smd: A(0.902,0) K(-0.902,0)
  silkscreen extent -1.59,-0.61 1.41,0.61, body extent -1.26,-0.48 1.26,0.48, height 0.84
0603_LED_GREEN [mm] "Resistor Footprint 0603"
  rect 0.8x1 smd: A(0.902,0) K(-0.902,0)
  silkscreen extent -1.59,-0.61 1.41,0.61, body extent -1.26,-0.48 1.26,0.48, height 0.84
0603_LED_RED [mm] "Resistor Footprint 0603"
  rect 0.8x1 smd: A(0.902,0) K(-0.902,0)
  silkscreen extent -1.59,-0.61 1.41,0.61, body extent -1.26,-0.48 1.26,0.48, height 0.84
0603_LED_Yellow [mm] "Resistor Footprint 0603"
  rect 0.8x1 smd: A(0.902,0) K(-0.902,0)
  silkscreen extent -1.59,-0.61 1.41,0.61, body extent -1.26,-0.48 1.26,0.48, height 0.84
0603_RES [mm] "Resistor Footprint 0603"
  rect 0.8x1 smd: 1(-0.902,0) 2(0.902,0)
  silkscreen extent -1.41,-0.61 1.41,0.61, body extent -1.26,-0.48 1.26,0.48, height 0.4
0603L [mil]
  rect 30x30 smd: 1(27.5,0) 2(-27.5,0)
  silkscreen extent -50,-20 50,20
CON_SAMTEC_TSW-102-07-G-S [mm]
  rect 1.85x1.85 hole 1 mask+0.05: 1(-1.27,0)
  round 1.85 hole 1 mask+0.05: 2(1.27,0)
  silkscreen extent -2.58,-1.3 2.58,1.3, body extent -2.67,-1.3 2.58,1.3, height 8.38
CON_SAMTEC_TSW-104-07-G-S [mm]
  rect 1.85x1.85 hole 1 mask+0.05: 1(-3.81,0)
  round 1.85 hole 1 mask+0.05: 2(-1.27,0) 3(1.27,0) 4(3.81,0)
  silkscreen extent -5.12,-1.3 5.12,1.3, body extent -5.21,-1.37 5.18,1.37, height 8.38
CON_TAG-C_TC2050-IDC-NL [mm]
  round 0.9 smd paste-9 mask+0.05: 1(-2.54,-0.635)
  round 0.9 smd paste-0.9 mask+0.05: 2(-1.27,-0.635) 3(0,-0.635) 4(1.27,-0.635) 5(2.54,-0.635) 6(2.54,0.635) 7(1.27,0.635) 8(0,0.635) 9(-1.27,0.635) 10(-2.54,0.635)
  round 0 hole 1.1 unplated mask+0.05: 11(-3.81,0) 12(3.81,-1.015) 13(3.81,1.015)
  Multi-Layer keep-out circle w0.01: c-3.81,0 r0.75
  Multi-Layer keep-out circle w0.01: c3.81,1.015 r0.75
  Multi-Layer keep-out circle w0.01: c3.81,-1.015 r0.75
  silkscreen extent -6.22,-3.4 6.22,3.33
CON_USBMICROAB_MOLEX_47590-0001_H3 [mm]
  rect 0.4x1.35 smd mask+0.05: 1(1.3,4.125) 2(0.65,4.125) 3(0,4.125) 4(-0.65,4.125) 5(-1.3,4.125)
  oval 1.05x1.25 hole 0.65 slot 0.85 at 90 deg mask+0.05: 6(-2.225,4.45) 7(2.225,4.45)
  rrect50% 1.375x1.9 hole 0.6 slot 1.3 at 90 deg copper offset 0.188,0 mask+0.05: 8(-4.175,1.45)
  rrect50% 1.375x1.9 hole 0.6 slot 1.3 at 90 deg copper offset -0.188,0 mask+0.05: 9(4.175,1.45)
  rect 2.9x1.9 smd mask+0.05: 10(0,1.45)
  oval 0.85x2.425 hole 0.85 slot 2.425 at 90 deg unplated mask+0.1: 11(-2.375,0.8) 12(2.375,0.8)
  silkscreen extent -4.1,-1.3 4.1,4.3, body extent -4.32,-1.36 4.33,4.6, height 3
CON_USBMICROB_MOLEX_105017-0001_H2P90 [mm]
  rect 0.4x1.35 smd mask+0.05: 1(-1.3,4.15) 2(-0.65,4.15) 3(0,4.15) 4(0.65,4.15) 5(1.3,4.15)
  round 1.5 hole 0.9 mask+0.05: 6(-2.5,4.15) 7(2.5,4.15)
  oval 1.2x1.9 hole 0.6 slot 1.3 at 90 deg mask+0.05: 8(3.5,1.45) 9(-3.5,1.45)
  rect 1.5x1.9 smd mask+0.05: 10(-1,1.45) 11(1,1.45)
  Top Layer region: -3.5,2.4 -2.3,2.4 -2.3,0.5 -3.5,0.5 -3.5,2.4
  Top Layer region: 2.3,2.4 3.5,2.4 3.5,0.5 2.3,0.5 2.3,2.4
  silkscreen extent -4,-0.7 4,4.6, body extent -4.1,-1.15 4.1,4.66, height 2.9
CRY_NX3215SA_2P [mm]
  rect 1x1.8 smd mask+0.05: 1(-1.25,0) 2(1.25,0)
  body extent -1.65,-0.8 1.65,0.8, height 0.9
CRY_NX3225GD_2P [mm]
  rect 1.5x2.7 smd mask+0.05: 1(-0.95,0) 2(0.95,0)
  silkscreen extent -0.1,-1.3 0.1,1.3, body extent -1.65,-1.3 1.65,1.3, height 1
DIO_SOD323 [mm]
  rect 1.06x0.54 smd mask+0.05: 1(-1.07,0) 2(1.07,0)
  silkscreen extent -0.9,-0.72 0.9,0.72, body extent -1.3,-0.78 1.3,0.78, height 1.17
ESD_FLIP-CHIP-BGA11_1P44X1P94_P050 [mm]
  round 0.3 smd paste+0 mask+0.05: A2(0,0.75) A3(0.5,0.75) B1(-0.5,0.25) B2(0,0.25) B3(0.5,0.25) C1(-0.5,-0.25) C2(0,-0.25) C3(0.5,-0.25) D1(-0.5,-0.75) D2(0,-0.75) D3(0.5,-0.75)
  silkscreen extent -0.9,-1 0.75,1.15, body extent -0.7,-0.95 0.7,0.95, height 0.7
F-V50XC-1X06R-LF [mm] "Connector 6pts, 2.54mm  female smd"
  rect 1.02x2.7 smd: 1(6.35,-1.35) 3(1.27,-1.35) 5(-3.81,-1.35)
  rect 1.02x2.25 smd: 2(3.81,1.09) 4(-1.27,1.09) 6(-6.35,1.09)
  silkscreen extent -8.8,-3.32 8.8,2.17, body extent -8,-1.27 8,1.24, height 9.02
F-V50XC-1X08R-LF#1 [mm] "Connector 8pts, 2.54mm  female smd"
  rect 1.02x2.7 smd: 1(8.89,-1.35) 2(6.35,1.35) 3(3.81,-1.35) 4(1.27,1.35) 5(-1.27,-1.35) 7(-6.35,-1.35)
  rect 1.02x2.25 smd: 6(-3.81,1.09) 8(-8.89,1.09)
  silkscreen extent -10.6,-3.32 10.6,2.15, body extent -10.54,-1.24 10.49,1.27, height 9.02
F-V50XC-1X08R-LF#2 [mm] "Connector 8pts, 2.54mm  female smd"
  rect 1.02x2.7 smd: 1(8.89,-1.35) 3(3.81,-1.35) 4(1.27,1.35) 5(-1.27,-1.35) 6(-3.81,1.35) 7(-6.35,-1.35) 8(-8.89,1.35)
  rect 1.02x2.5 smd: 2(6.35,1.15)
  silkscreen extent -10.6,-3.32 10.6,2.15, body extent -10.54,-1.24 10.49,1.27, height 9.02
F-V50XC-1X10R-LF [mm] "Connector 10pts, 2.54mm  female smd"
  rect 1.02x2.7 smd: 1(11.43,-1.35) 2(8.89,1.35) 3(6.35,-1.35) 4(3.81,1.35) 5(1.27,-1.35) 6(-1.27,1.35) 7(-3.81,-1.35) 8(-6.35,1.35) 9(-8.89,-1.35) 10(-11.43,1.35)
  silkscreen extent -13,-3.32 13.2,2.15, body extent -13.08,-1.27 13.13,1.24, height 9.02
"HCLGA-4LD 3x4x1" [mm] "HCLGA-4LD 3x4x1mm (MP34DT01_Microphone MEMS)"
  rect 0.4x0.95 smd mask+0.02: 1(-0.425,0.675) 2(-0.425,-0.675) 3(0.425,-0.675) 4(0.425,0.675)
  rect 0.35x2.3 smd mask+0.02: 5(-1.225,0) 5(1.225,0)
  rect 1.3x0.35 smd mask+0.02: 5(0,1.725) 5(0,-1.725)
  silkscreen extent -1.91,-2 1.5,2.44, body extent -1.5,-2.01 1.5,2.01, height 1.01
"Header F 2x6x2.54 TH H PMOD" [mm] "2x6x2.54 Header TH H Female PMOD Warning Specific Pinout"
  rect 1.8x1.8 hole 1: 1(0,0)
  round 1.8 hole 1: 2(2.54,0) 3(5.08,0) 4(7.62,0) 5(10.16,0) 6(12.7,0) 7(0,2.54) 8(2.54,2.54) 9(5.08,2.54) 10(7.62,2.54) 11(10.16,2.54) 12(12.7,2.54)
  silkscreen extent -1.47,-1.43 14.05,12.7, body extent -1.42,-0.32 14.07,12.71, height 5.04
"Header M 2x5x2.54 TH V" [mm] "2x5x2.54 Header TH V Male"
  rect 1.8x1.8 hole 1: 1(0,0)
  round 1.8 hole 1: 2(0,2.54) 3(2.54,0) 4(2.54,2.54) 5(5.08,0) 6(5.08,2.54) 7(7.62,0) 8(7.62,2.54) 9(10.16,0) 10(10.16,2.54)
  silkscreen extent -1.47,-1.43 11.56,3.97, body extent -1.3,-1.24 11.4,3.84, height 8.5
HLGA6L-2x2x0.9 [mm] "HLGA6L 2x2x0.9mm pitch1mm"
  rect 0.4x0.35 smd mask+0.05: 1(-0.675,0.5) 2(-0.675,-0.5) 4(0.675,-0.5) 5(0.675,0.5)
  rect 0.35x0.4 smd mask+0.05: 3(0,-0.675) 6(0,0.675)
  silkscreen extent -1.45,-1.02 1.02,1.46, body extent -1.02,-1.02 1.02,1.02, height 1
HLGA10L-2X2X0.76 [mm] "HLGA-10L 2x2x0.76mm pitch 0.5mm"
  oct 0.275x0.25 smd paste+0 mask+0.05: 1(-0.763,0.25)
  rect 0.275x0.25 smd paste+0 mask+0.05: 2(-0.763,-0.25) 6(0.763,-0.25) 7(0.763,0.25)
  rect 0.25x0.275 smd paste+0 mask+0.05: 3(-0.5,-0.763) 4(0,-0.763) 5(0.5,-0.763) 8(0.5,0.763) 9(0,0.763) 10(-0.5,0.763)
  silkscreen extent -1.5,-1 1,1, body extent -1.02,-1.02 1.02,1.02, height 0.77
ICC_LQFP48_7X7_P050 [mm]
  rect 0.3x1.2 smd mask+0.05: 1(-2.75,-4.25) 2(-2.25,-4.25) 3(-1.75,-4.25) 4(-1.25,-4.25) 5(-0.75,-4.25) 6(-0.25,-4.25) 7(0.25,-4.25) 8(0.75,-4.25) 9(1.25,-4.25) 10(1.75,-4.25) 11(2.25,-4.25) 12(2.75,-4.25) 25(2.75,4.25) 26(2.25,4.25) 27(1.75,4.25) 28(1.25,4.25) 29(0.75,4.25) 30(0.25,4.25) 31(-0.25,4.25) 32(-0.75,4.25) 33(-1.25,4.25) 34(-1.75,4.25) 35(-2.25,4.25) 36(-2.75,4.25)
  rect 1.2x0.3 smd mask+0.05: 13(4.25,-2.75) 14(4.25,-2.25) 15(4.25,-1.75) 16(4.25,-1.25) 17(4.25,-0.75) 18(4.25,-0.25) 19(4.25,0.25) 20(4.25,0.75) 21(4.25,1.25) 22(4.25,1.75) 23(4.25,2.25) 24(4.25,2.75) 37(-4.25,2.75) 38(-4.25,2.25) 39(-4.25,1.75) 40(-4.25,1.25) 41(-4.25,0.75) 42(-4.25,0.25) 43(-4.25,-0.25) 44(-4.25,-0.75) 45(-4.25,-1.25) 46(-4.25,-1.75) 47(-4.25,-2.25) 48(-4.25,-2.75)
  silkscreen extent -3.52,-3.52 3.52,3.52, body extent -4.5,-4.5 4.5,4.5, height 1.6
ICC_SO8_5X4_P127 [mm]
  rect 0.7x1.75 smd mask+0.05: 1(-1.905,-2.375) 2(-0.635,-2.375) 3(0.635,-2.375) 4(1.905,-2.375) 5(1.905,2.375) 6(0.635,2.375) 7(-0.635,2.375) 8(-1.905,2.375)
  silkscreen extent -2.58,-2 2.58,2, body extent -2.57,-3 2.57,3, height 1.75
ISM43362-M3G-L44 [mm] "ISM43362-M3G-L44 Module Wifi 802.11 bgn"
  rect 0.84x0.84 smd: 1(8.742,6.88) 2(7.285,6.88) 3(5.828,6.88) 4(4.371,6.88) 5(2.914,6.88) 6(1.457,6.88) 7(0,6.88) 8(-1.457,6.88) 9(-2.914,6.88) 10(-4.371,6.88) 11(-5.828,6.88) 12(-7.285,6.88) 13(-8.742,6.88) 14(-9.942,5.68) 15(-9.942,4.26) 16(-9.942,2.84) 17(-9.942,1.42) 18(-9.942,0) 19(-9.942,-1.42) 20(-9.942,-2.84) 21(-9.942,-4.26) 22(-9.942,-5.68) 23(-8.742,-6.88) 24(-7.285,-6.88) 25(-5.828,-6.88) 26(-4.371,-6.88) 27(-2.914,-6.88) 28(-1.457,-6.88) 29(0,-6.88) 30(1.457,-6.88) 31(2.914,-6.88) 32(4.371,-6.88) 33(5.828,-6.88) 34(7.285,-6.88) 35(8.742,-6.88) 36(9.942,-5.68) 37(9.942,-4.26) 38(9.942,-2.84) 39(9.942,-1.42) 40(9.942,0) 41(9.942,1.42) 42(9.942,2.84) 43(9.942,4.26) 44(9.942,5.68)
  silkscreen extent -10.65,-9.63 19.64,9.73, body extent -10.64,-7.32 19.66,7.32, height 2.7
LED_BI-GR_HSMF-A201-A00J1 [mm]
  rect 1.1x1.5 smd mask+0.05: 1(-0.75,-1.5) 2(-0.75,1.5) 3(0.75,1.5) 4(0.75,-1.5)
  silkscreen extent -1.65,-1.85 1.65,1.85, body extent -1.5,-1.85 1.5,1.85, height 2.1
LGA12-optical [mm] "VL53L0X : World smallest Time-of-Flight ranging and gesture detection sensor"
  rect 0.5x0.5 smd: 1(1.6,-0.8) 2(0.8,-0.8) 3(0,-0.8) 4(-0.8,-0.8) 5(-1.6,-0.8) 6(-1.6,0) 7(-1.6,0.8) 8(-0.8,0.8) 9(0,0.8) 10(0.8,0.8) 11(1.6,0.8) 12(1.6,0)
  rect 0.08x0.25 smd: 1(1.89,-0.675)
  silkscreen extent -2.2,-1.65 2.67,1.2, body extent -2.18,-1.22 2.21,1.19, height 1.01
LGA14L-2.5X3X0.86p0.5 [mm] "LGA14 2.5x3x0.86mm pitch0.5mm"
  rect 0.75x0.3 smd mask+0.05: 1(-1.33,0.75) 2(-1.33,0.25) 3(-1.33,-0.25) 4(-1.33,-0.75) 8(1.33,-0.75) 9(1.33,-0.25) 10(1.33,0.25) 11(1.33,0.75)
  rect 0.3x0.75 smd mask+0.05: 5(-0.5,-1.1) 6(0,-1.1) 7(0.5,-1.1) 12(0.5,1.1) 13(0,1.1) 14(-0.5,1.1)
  silkscreen extent -2.16,-1.25 1.52,1.8, body extent -1.52,-1.27 1.52,1.27, height 0.9
"LOGO CE" [mm]
  silkscreen extent -3.27,-3.31 4.33,3.3
LOGO_ST_Size3 [mm]
  silkscreen extent -4.5,-2.36 4.7,2.57
"LQFP100 14x14x1.6" [mm] "LQFP100 14x14mm low profile 1.6mm"
  rect 1.2x0.3 smd: 1(-7.75,6) 2(-7.75,5.5) 3(-7.75,5) 4(-7.75,4.5) 5(-7.75,4) 6(-7.75,3.5) 7(-7.75,3) 8(-7.75,2.5) 9(-7.75,2) 10(-7.75,1.5) 11(-7.75,1) 12(-7.75,0.5) 13(-7.75,0) 14(-7.75,-0.5) 15(-7.75,-1) 16(-7.75,-1.5) 17(-7.75,-2) 18(-7.75,-2.5) 19(-7.75,-3) 20(-7.75,-3.5) 21(-7.75,-4) 22(-7.75,-4.5) 23(-7.75,-5) 24(-7.75,-5.5) 25(-7.75,-6) 51(7.75,-6) 52(7.75,-5.5) 53(7.75,-5) 54(7.75,-4.5) 55(7.75,-4) 56(7.75,-3.5) 57(7.75,-3) 58(7.75,-2.5) 59(7.75,-2) 60(7.75,-1.5) 61(7.75,-1) 62(7.75,-0.5) 63(7.75,0) 64(7.75,0.5) 65(7.75,1) 66(7.75,1.5) 67(7.75,2) 68(7.75,2.5) 69(7.75,3) 70(7.75,3.5) 71(7.75,4) 72(7.75,4.5) 73(7.75,5) 74(7.75,5.5) 75(7.75,6)
  rect 0.3x1.2 smd: 26(-6,-7.75) 27(-5.5,-7.75) 28(-5,-7.75) 29(-4.5,-7.75) 30(-4,-7.75) 31(-3.5,-7.75) 32(-3,-7.75) 33(-2.5,-7.75) 34(-2,-7.75) 35(-1.5,-7.75) 36(-1,-7.75) 37(-0.5,-7.75) 38(0,-7.75) 39(0.5,-7.75) 40(1,-7.75) 41(1.5,-7.75) 42(2,-7.75) 43(2.5,-7.75) 44(3,-7.75) 45(3.5,-7.75) 46(4,-7.75) 47(4.5,-7.75) 48(5,-7.75) 49(5.5,-7.75) 50(6,-7.75) 76(6,7.75) 77(5.5,7.75) 78(5,7.75) 79(4.5,7.75) 80(4,7.75) 81(3.5,7.75) 82(3,7.75) 83(2.5,7.75) 84(2,7.75) 85(1.5,7.75) 86(1,7.75) 87(0.5,7.75) 88(0,7.75) 89(-0.5,7.75) 90(-1,7.75) 91(-1.5,7.75) 92(-2,7.75) 93(-2.5,7.75) 94(-3,7.75) 95(-3.5,7.75) 96(-4,7.75) 97(-4.5,7.75) 98(-5,7.75) 99(-5.5,7.75) 100(-6,7.75)
  silkscreen extent -7.87,-6.3 6.3,6.82, body extent -7,-7 7,7, height 1.65
MOS_SOT23-5L [mm]
  rect 0.6x1.3 smd mask+0.05: 1(-0.95,-1.1) 2(0,-1.1) 3(0.95,-1.1) 4(0.95,1.1) 5(-0.95,1.1)
  silkscreen extent -1.6,-0.95 1.6,0.97, body extent -1.52,-1.25 1.52,1.25, height 1.45
PTB [mm]
  rect 2x1 smd: 1(0,0)
  silkscreen extent -1.1,-0.6 1.1,0.6
REG_SOT23-5L [mm]
  rect 0.6x1.3 smd mask+0.05: 1(-0.95,-1.1) 2(0,-1.1) 3(0.95,-1.1) 4(0.95,1.1) 5(-0.95,1.1)
  silkscreen extent -1.6,-0.95 1.6,0.97, body extent -1.52,-1.25 1.52,1.25, height 1.1
REG_SOT223-TAB [mm]
  rect 1.5x1.65 smd mask+0.05: 1(-2.3,-3.175) 2(0,-3.175) 3(2.3,-3.175)
  rect 3.5x1.65 smd mask+0.05: 4(0,3.175)
  silkscreen extent -3.35,-2.15 3.35,2.12, body extent -3.35,-3.48 3.35,3.48, height 1.8
SB [mil]
  round 10 smd paste-10: 1(-19.68,0)
  round 10 smd paste-10.08: 2(23.62,0)
  Top Layer region: -5.91,19.68 13.78,0 -5.91,-19.69 47.24,-19.69 47.24,19.68
  Top Layer region: -47.24,-19.69 -47.24,19.68 -15.75,19.68 3.94,0 -15.75,-19.69
  silkscreen extent -50,-23 50,23
SOP8 [mm] "SOP, 8-Leads, Body 5.0x4.0mm (max), Pitch 1.27mm, IPC Medium Density"
  rect 2.2x0.6 smd: 1(-2.425,1.905)
  oval 2.2x0.6 smd: 2(-2.425,0.635) 3(-2.425,-0.635) 4(-2.425,-1.905) 5(2.425,-1.905) 6(2.425,-0.635) 7(2.425,0.635) 8(2.425,1.905)
  silkscreen extent -2.64,-2.54 2.03,3.02, body extent -2.97,-2.45 3.17,2.44, height 1.73
SOP8L [mm] "SOP, 8-Leads, Body 5.0x4.0mm (max), Pitch 1.27mm, IPC Medium Density"
  rect 2.2x0.6 smd: 1(-3.32,1.905)
  oval 2.2x0.6 smd: 2(-3.32,0.635) 3(-3.32,-0.635) 4(-3.32,-1.905) 5(3.32,-1.905) 6(3.32,-0.635) 7(3.32,0.635) 8(3.32,1.905)
  silkscreen extent -2.64,-2.54 2.03,3.02, body extent -2.97,-2.45 3.17,2.44, height 1.73
SOT23-3 [mm]
  rect 0.9x0.95 smd: 1(-0.95,-2.35) 2(0.95,-2.35) 3(0,0)
  silkscreen extent -1.9,-3.35 1.3,0, body extent -1.27,-1.8 1.32,-0.51, height 1.05
SOT23-5 [mil]
  rect 50x20 smd: 1(-50,37.5) 2(-50,0.5) 3(-50,-37.5) 4(50,-37.5) 5(50,37.5)
  silkscreen extent -104,-7 55,77, body extent -32,-57 32,57, height 47
SOT223_SC73 [mil]
  rect 39x59 smd: 1(-90,-124) 2(0,-124) 3(90,-124)
  rect 129x59 smd: 2(0,124)
  silkscreen extent -140,-71 138,70, body extent -128,-136 128,138, height 65
"Spacer+Nut M3" [mm] "Spacer+Nut M3 Mechanical Only"
  body extent -3.17,-2.75 3.18,2.75, height 5.5
SPBTLE-RF [mm]
  rect 1.6x1 smd: 1(0,0) 2(0,-1.27) 3(0,-2.54) 4(0,-3.81) 5(0,-5.08) 7(13.5,-5.08) 8(13.5,-3.81) 9(13.5,-2.54) 10(13.5,-1.27) 11(13.5,0)
  rect 1x1.6 smd: 6(4,-6.08)
  silkscreen extent -0.69,-5.88 13.5,5.72, body extent -0.03,-5.89 13.51,5.72, height 2.1
SPSGRF [mm]
  rect 1.6x1 smd: 1(0,0) 2(0,-1.27) 3(0,-2.54) 4(0,-3.81) 5(0,-5.08) 7(13.5,-5.08) 8(13.5,-3.81) 9(13.5,-2.54) 10(13.5,-1.27) 11(13.5,0)
  rect 1x1.6 smd: 6(4,-6.08)
  silkscreen extent -0.64,-5.88 13.5,5.72, body extent 0.03,-5.89 13.51,5.72, height 2.1
"SWI_WEALTHMETAL_TD-0341_4P - BACK" [mm] "SMD Push Button with Back Plastic"
  rect 1.52x2.16 smd mask+0.05: 1(-2.25,-4.75) 1(-2.25,4.75) 2(2.25,-4.75) 2(2.25,4.75)
  silkscreen extent -3,-3.5 3,3.5, body extent -3,-5 3,5, height 6
"SWI_WEALTHMETAL_TD-0341_4P - BLUE" [mm] "SMD Push Button with Back Plastic"
  rect 1.52x2.16 smd mask+0.05: 1(-2.25,-4.75) 1(-2.25,4.75) 2(2.25,-4.75) 2(2.25,4.75)
  silkscreen extent -3,-3.5 3,3.5, body extent -3,-5 3,5, height 6
SYMBOL_ESD [mm]
  silkscreen extent -3.46,-2.52 3.25,3.62
SYMBOL_RoHS [mm]
  silkscreen extent 0,0 9.5,6
VFLGA12-2x2x1 [mm] "LGA12 2x2x1mm"
  rect 0.3x0.3 smd mask+0.05: 1(-0.75,0.75) 2(-0.75,0.25) 3(-0.75,-0.25) 4(-0.75,-0.75) 5(-0.25,-0.75) 6(0.25,-0.75) 7(0.75,-0.75) 8(0.75,-0.25) 9(0.75,0.25) 10(0.75,0.75) 11(0.25,0.75) 12(-0.25,0.75)
  silkscreen extent -1.47,-1.02 1.02,1.45, body extent -1.02,-1.02 1.02,1.02, height 1.1

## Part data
B1 B2: library part SW-PB_2, "Push-button SMD"
C1 C2 C3 C4 C5 C6 C7 C8 C9 C10 C11 C12 C13 C14 C15 C16 C17 C18 C19 C20 C21 C22 C23 C24 C25 C26 C27 C28 C29 C30 C31 C32 C33 C34 C35 C36 C37 C38 C39 C40 C41 C42 C43 C44 C45 C46 C47 C48 C49 C50 C51 C52 C53 C54 C55 C56 C57 C58 C59 C60 C61 C62 C63 C64 C65 C66 C67 C68 C69 C70 C71 C72 C73 C74 C75 C76: library part CAP_NPOL, "Capacitor_not polarized"
CN1: "Header, 10-Pin, SMD, Single row,female"
CN2 CN3: "Header, 8-Pin, SMD, Single row,female"
CN4: "Header, 6-Pin, SMD, Single row,female"
CN5: library part Tag-10-C, "Tag_Connector Header, 10-Pin, Dual row No legs"
CN6: library part "Header 2 pins", "Header 2 pins"
CN7: "USB-MICRO-B, 1050170001, SMT, MOLEX"
CN8: library part "Header 4", "Header, 4-Pin"
CN9: "USB-MICRO-AB, 47590-0001, SMT, MOLEX"
CN10: "PMOD Connector Warning Specific Pinout"
JP5 JP6 JP7 JP8: library part TSW-102-07-x-S, "Connector jumper 1 position"
L1 L2: library part Inductor, "Inductor"
LD1 LD2 LD3 LD4 LD5 LD7 LD8 LD9: "Light-Emitting Diode"
LD6: "Bicolor Led"
M1: library part SPBTLE-RF, "SPBTLE-RF"
M2: "ISM43362-M3G-L44 Wifi Module 802.11 bgn"
M3: "SPSGRF-915or SPSGRF-868"
Q1 Q2: "BSR14 NPN switching transistor SOT23 (Marking U8)"
R1 R2 R3 R4 R5 R6 R7 R8 R9 R10 R11 R12 R13 R14 R15 R16 R18 R19 R20 R21 R22 R23 R24 R25 R26 R27 R28 R29 R30 R31 R32 R33 R34 R35 R36 R38 R39 R40 R41 R42 R43 R44 R45 R46 R47 R48 R49 R50 R51 R52 R53 R54 R55 R56 R57 R58 R59 R61 R62 R64 R65 R66 R67: library part RES, "Resistor"
SB1 SB2 SB3 SB4 SB5 SB6 SB7 SB8 SB9 SB10 SB11 SB12 SB13 SB14 SB15 SB16 SB17 SB18 SB19 SB20 SB21: library part Strap2, "Solder Jumper"
TP1 TP2 TP3 TP4 TP5 TP6: "Point de test"
U2 U10: library part MP34DT01, "MEMS audio microphone"
U3: "Accelero + Gyro MEMS (6 Axis)"
U4: "Proximity sensor MEMS"
U5 U7: "IC,Sensor"
U6: "Humidity + Temp MEMS"
U8: "M24SR64-Y  64K_EEPROM NFC/RFID"
U9: library part STSAFE-A100, "STSAFE-A100"
U11: "MX25R6435F Serial Flash Memory 64M"
U12: "LT1963EST-3.3 LDO Low Noise 1.5A fast Transient Response"
U13: "IC REG LDO 5V 0.8A SOT223"
U14: "LOW DROP FIXED AND ADJUSTABLE POSITIVE VOLTAGE REGULATORS (3.3 Volts)"
U15: "Medium-density performance line ARM-based 32-bit MCU with 128KB Flash"
U16: "Ultra low drop-low noise BiCMOS voltage, regulators low ESR capacitors compatible"
U17: "1.2 A current limited high-side power switch with thermal shutdown"
U18 U20: "2-line IPAD, EMI filter including ESD protection"
U19: "Enhanced single channel power switches"
U21: "TSV631AILT  Rail-to-rail input/output, 60 µA, 880 kHz, 5 V CMOS  operational amplifiers"
X1 X3: library part XTAL_8M_NX3225GD, "Crystal 8Mhz, 8pF, -+50PPM, SMD"
X2: library part XTAL_32K_NX3215SA, "Crystal 32.768kHz, 6pF, -+20PPM, R=50K, SMD"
